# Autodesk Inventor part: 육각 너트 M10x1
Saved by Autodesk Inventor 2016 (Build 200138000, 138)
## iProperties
Created: 2024-08
Part Number: 육각 너트 M10x1
Material: 일반
Description: 6각 너트 및 6각 가는 너트
Document SubType Name: Modeling
Designer: pc-2
Density: 1 g/cm^3
Appearance: 기본값
Author: jhkim
Sending System: Autodesk Inventor 2025
Preprocessor: ST-DEVELOPER v20
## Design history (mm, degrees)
node "육각 너트 M10x11"
node "솔리드1"
body "Solid1"
